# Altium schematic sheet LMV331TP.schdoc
size 127 x 101 mm
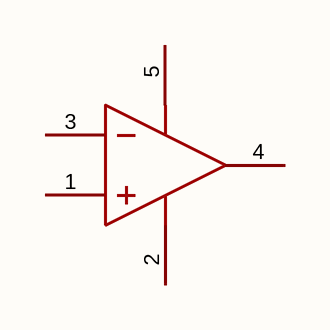
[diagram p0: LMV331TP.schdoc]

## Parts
U?  lmv331tp  [SOT-23-5_L2.9-W1.6-P0.95-LS2.7-BR]  (value not drawn)

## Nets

Not connected (* = marked no-connect by the designer): U? 1(+IN) 2(V-) 3(-IN) 4(OUT) 5(V+)

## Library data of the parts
U? = lmv331tp: 比较器数:单路;输入失调电压(Vos):800uV;输入偏置电流(Ib):2pA;轨到轨:轨到轨输入;; Manufacturer: TECH PUBLIC(台舟); AddInBom: yes; ModelId: 5bdb685575ac4afdbc0929a885e75187; ModelTransform: 114.173,110.236,0,90,0,0,0,0,0; Number of Channels: 单路; Vos - Input Offset Voltage: 800uV; Ib - Input Bias Current: 2pA; Propagation Delay Time: 950ns; Output Type: 开漏; Rail to Rail: 轨到轨输入; Quiescent Current: 50uA; Maximum Power Supply Range (Vdd-Vss): 7V; Single Supply: 1.8V~5.5V; Input Offset Voltage Drift(Vos TC): 0.8uV/℃; Input Offset Current(Ios): 1pA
